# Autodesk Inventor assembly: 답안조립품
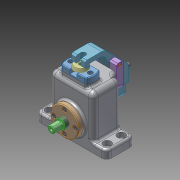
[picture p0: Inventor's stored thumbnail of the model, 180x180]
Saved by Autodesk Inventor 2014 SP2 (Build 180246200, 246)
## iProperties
Created: 2023-12
Part Number: 답안조립품
Document SubType Name: Assembly
Designer: 거성
Author: 거성
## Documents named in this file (14)
- C:\Users\거성\Desktop\731208V1004\답안조립품.iam
- C:\Users\거성\Desktop\731208V1004\본체.ipt
- C:\Users\거성\Desktop\731208V1004\가이드 부시.ipt
- C:\Users\거성\Desktop\731208V1004\조절 부시.ipt
- C:\Users\거성\Desktop\731208V1004\클램프 샤프트.ipt
- C:\Users\거성\Desktop\731208V1004\고정대.ipt
- C:\Users\거성\Desktop\731208V1004\가공품.ipt
- C:\Users\거성\Desktop\731208V1004\클램프.ipt
- C:\Users\거성\Desktop\731208V1004\브라켓.ipt
- C:\Users\거성\Desktop\731208V1004\육각 머리 볼트 M6 x 12.ipt
- C:\Users\거성\Desktop\731208V1004\육각 소켓 머리 볼트 M3 x 30.ipt
- C:\Users\거성\Desktop\731208V1004\스프링.ipt
- C:\Users\거성\Desktop\731208V1004\육각 소켓 머리 볼트 M3 x 8.ipt
- C:\Users\거성\Desktop\731208V1004\핀.ipt
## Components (4 placed, 4 different names)
1. 가이드 부시:1 — 각도:1
2. 고정대:1
3. 가공품:1
4. 핀:1 — 플러쉬:1
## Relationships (2: Angle 1, Flush 1)
- 각도:1 [Angle]: 가이드 부시:1
- 플러쉬:1 [Flush]: 핀:1
